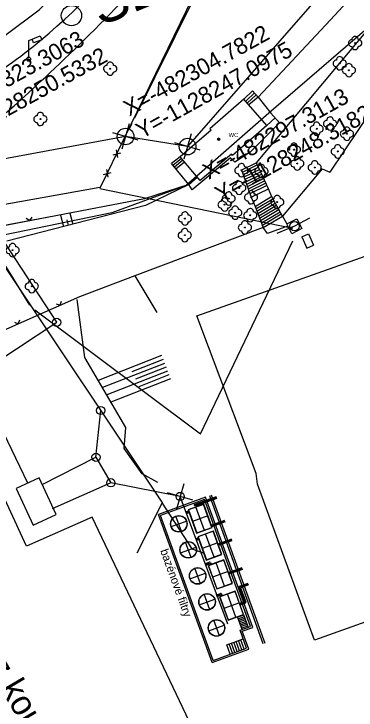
# Model space of a CAD drawing. Extents: x -483721 to -481876, y -1129170 to -1127366.
# Drawn here: x -482318.3 to -482277, y -1128316.3 to -1128232.3 of the extents above; entities that cross this region are included whole.
import ezdxf

# ---------------------------------------------------------------- set-up
doc = ezdxf.new("R2010")
doc.units = 0
for name, color, linetype in [('1 Terenni Hrany', 7, 'Continuous'), ('FILTRACE', 7, 'Continuous'), ('Hranice parcel', 7, 'Continuous'), ('kresba', 7, 'Continuous'), ('OSTATNI', 7, 'Continuous'), ('SO 01', 7, 'Continuous'), ('SO 01_zrušeno', 7, 'Continuous'), ('SO 02', 7, 'Continuous'), ('SO 02_odpad', 7, 'Continuous'), ('SO 02_plot', 7, 'Continuous'), ('SO 02_prací', 7, 'Continuous'), ('SO 02_upravená', 7, 'Continuous'), ('SO 04', 7, 'Continuous'), ('SO 07', 7, 'Continuous'), ('STROM', 7, 'Continuous'), ('U_IGP', 7, 'Continuous'), ('u_SO_POPIS_1000', 7, 'Continuous'), ('u_vytyčení', 7, 'Continuous'), ('ˇ12', 7, 'Continuous')]:
    doc.layers.add(name, color=color, linetype=linetype)

# ---------------------------------------------------------------- blocks, each defined once
blk = doc.blocks.new('STROM')
blk.add_circle((0, 0), 0.143)
for centre, start, end in [((-1.01, -0.04), 90.2896, 270.7727), ((-0.02, 1.01), 359.3339, 182.81), ((0, -0.99), 90.3571, 90.7727), ((-1.01, -0.04), 2.5539, 2.81), ((0.99, 0), 179.3339, 179.5894), ((-0.02, 1.01), 270.2896, 270.7197), ((0.99, 0), 270.3571, 90.7197), ((0, -0.99), 182.5539, 359.5894)]:
    blk.add_arc(centre, 1, start, end)
blk = doc.blocks.new('_X5')
for p, q in [((13.91, 13.06), (14.17, 13.32)), ((14.18, 12.81), (13.91, 13.07)), ((13.92, 13.02), (14.21, 13.31)), ((13.92, 13.11), (14.12, 13.31)), ((14.22, 12.81), (13.92, 13.11)), ((14.13, 12.81), (13.92, 13.03)), ((13.93, 12.98), (14.25, 13.3)), ((14.25, 12.82), (13.93, 13.15)), ((14.07, 12.83), (13.93, 12.96)), ((13.94, 12.95), (14.28, 13.29)), ((13.94, 13.18), (14.05, 13.29)), ((14.28, 12.84), (13.94, 13.18)), ((13.95, 12.92), (14.31, 13.27)), ((14.31, 12.85), (13.96, 13.21)), ((13.97, 12.9), (14.33, 13.25)), ((14.34, 12.87), (13.98, 13.23)), ((14.36, 12.9), (14, 13.25)), ((14, 12.87), (14.35, 13.23)), ((14.02, 12.85), (14.37, 13.21)), ((14.38, 12.92), (14.03, 13.27)), ((14.39, 12.95), (14.05, 13.29)), ((14.05, 12.84), (14.39, 13.18)), ((14.08, 12.82), (14.4, 13.15)), ((14.41, 12.98), (14.09, 13.3)), ((14.42, 13.02), (14.12, 13.31)), ((14.12, 12.81), (14.41, 13.11)), ((14.42, 13.06), (14.16, 13.32)), ((14.16, 12.81), (14.42, 13.07)), ((14.2, 12.81), (14.42, 13.02)), ((14.41, 13.11), (14.21, 13.31)), ((14.27, 12.83), (14.4, 12.96)), ((14.39, 13.18), (14.28, 13.29))]:
    blk.add_line(p, q)
blk = doc.blocks.new('BUDOVA')
blk.add_circle((0, -0.01), 0.253)
blk.add_blockref('_X5', (-14.17, -13.07))
blk = doc.blocks.new('LAMPA')
for p, q in [((0, 4.55), (2.79, 5.63)), ((2.79, 5.63), (3.13, 4.71)), ((0, 0.52), (0, 4.55)), ((1.17, 3.98), (0.84, 4.87)), ((3.13, 4.71), (1.17, 3.98))]:
    blk.add_line(p, q)
blk.add_circle((0, 0.02), 0.5)

msp = doc.modelspace()

# ---------------------------------------------------------------- linework, layer by layer
for p, q in [((-482307.86, -1128253.28), (-482295.68, -1128228.29)), ((-482307.9, -1128253.27), (-482358.09, -1128262.23)), ((-482307.881, -1128253.364), (-482284.63, -1128258.16)), ((-482307.87, -1128253.3), (-482307.87, -1128253.3)), ((-482303.39, -1128297.34), (-482300.38, -1128291.35))]:
    msp.add_line(p, q)
for points in [[(-482357.81, -1128262.3), (-482319.42, -1128262.72), (-482300.35, -1128291.33)], [(-482300.38, -1128291.35), (-482296.794, -1128296.846), (-482295.295, -1128297.398)]]:
    msp.add_lwpolyline(points)
at = {"layer": '1 Terenni Hrany'}
msp.add_lwpolyline([(-482352.607, -1128249.588), (-482341.55, -1128246.847), (-482332.308, -1128243.048), (-482323.52, -1128238.017), (-482315.2, -1128231.824), (-482308.051, -1128224.73), (-482304.891, -1128221.021), (-482300.175, -1128213.301)], dxfattribs=at)
at = {"layer": 'FILTRACE'}
for p, q in [((-482296.423, -1128291.481), (-482293.827, -1128290.541)), ((-482288.172, -1128308.339), (-482294.642, -1128290.464)), ((-482287.965, -1128308.264), (-482294.435, -1128290.389)), ((-482295.131, -1128290.641), (-482300.82, -1128292.7)), ((-482295.251, -1128290.897), (-482300.564, -1128292.82)), ((-482296.483, -1128291.609), (-482293.793, -1128290.635)), ((-482296.354, -1128291.669), (-482293.759, -1128290.729)), ((-482289.7, -1128306.233), (-482295.251, -1128290.897)), ((-482289.444, -1128306.353), (-482295.131, -1128290.641)), ((-482295.363, -1128291.469), (-482297.244, -1128292.15)), ((-482297.244, -1128292.15), (-482296.223, -1128294.971)), ((-482295.378, -1128291.501), (-482297.212, -1128292.165)), ((-482297.212, -1128292.165), (-482296.208, -1128294.939)), ((-482296.354, -1128291.669), (-482296.423, -1128291.481)), ((-482295.282, -1128294.631), (-482296.303, -1128291.81)), ((-482294.374, -1128294.275), (-482295.378, -1128291.501)), ((-482294.342, -1128294.29), (-482295.363, -1128291.469)), ((-482294.35, -1128310.575), (-482300.82, -1128292.7)), ((-482294.23, -1128310.319), (-482300.564, -1128292.82)), ((-482298.024, -1128294.783), (-482298.705, -1128292.902)), ((-482297.475, -1128292.393), (-482297.193, -1128292.291)), ((-482297.441, -1128292.487), (-482297.159, -1128292.385)), ((-482297.407, -1128292.581), (-482297.125, -1128292.479)), ((-482294.853, -1128292.88), (-482296.733, -1128293.56)), ((-482299.305, -1128294.183), (-482297.424, -1128293.502)), ((-482294.451, -1128293.989), (-482292.796, -1128293.39)), ((-482294.417, -1128294.083), (-482292.762, -1128293.484)), ((-482294.383, -1128294.177), (-482292.728, -1128293.578)), ((-482296.223, -1128294.971), (-482294.342, -1128294.29)), ((-482296.208, -1128294.939), (-482294.374, -1128294.275)), ((-482294.189, -1128294.713), (-482296.07, -1128295.394)), ((-482294.204, -1128294.745), (-482296.037, -1128295.409)), ((-482293.2, -1128297.519), (-482294.204, -1128294.745)), ((-482293.168, -1128297.534), (-482294.189, -1128294.713)), ((-482296.301, -1128295.637), (-482296.018, -1128295.535)), ((-482296.267, -1128295.731), (-482295.984, -1128295.629)), ((-482296.07, -1128295.394), (-482295.048, -1128298.215)), ((-482296.037, -1128295.409), (-482295.033, -1128298.183)), ((-482294.108, -1128297.875), (-482295.129, -1128295.054)), ((-482296.887, -1128297.923), (-482297.568, -1128296.043)), ((-482296.232, -1128295.825), (-482295.95, -1128295.723)), ((-482293.678, -1128296.124), (-482295.559, -1128296.804)), ((-482293.634, -1128296.246), (-482291.979, -1128295.647)), ((-482293.6, -1128296.34), (-482291.945, -1128295.741)), ((-482293.566, -1128296.434), (-482291.911, -1128295.835)), ((-482298.168, -1128297.323), (-482296.288, -1128296.643)), ((-482295.048, -1128298.215), (-482293.168, -1128297.534)), ((-482295.033, -1128298.183), (-482293.2, -1128297.519)), ((-482295.208, -1128298.656), (-482294.691, -1128298.468)), ((-482295.174, -1128298.75), (-482294.657, -1128298.562)), ((-482295.14, -1128298.844), (-482294.717, -1128298.69)), ((-482292.926, -1128298.202), (-482294.807, -1128298.883)), ((-482294.807, -1128298.883), (-482293.786, -1128301.703)), ((-482292.941, -1128298.234), (-482294.775, -1128298.898)), ((-482294.775, -1128298.898), (-482293.771, -1128301.671)), ((-482294.717, -1128298.69), (-482294.666, -1128298.831)), ((-482294.657, -1128298.562), (-482294.572, -1128298.797)), ((-482294.563, -1128298.528), (-482294.478, -1128298.763)), ((-482292.845, -1128301.363), (-482293.867, -1128298.542)), ((-482291.937, -1128301.008), (-482292.941, -1128298.234)), ((-482291.905, -1128301.023), (-482292.926, -1128298.202)), ((-482297.031, -1128300.464), (-482295.151, -1128299.783)), ((-482295.751, -1128301.064), (-482296.431, -1128299.183)), ((-482292.416, -1128299.612), (-482294.296, -1128300.293)), ((-482292.382, -1128299.706), (-482290.727, -1128299.107)), ((-482292.348, -1128299.8), (-482290.693, -1128299.201)), ((-482292.314, -1128299.894), (-482290.659, -1128299.295)), ((-482293.786, -1128301.703), (-482291.905, -1128301.023)), ((-482293.771, -1128301.671), (-482291.937, -1128301.008)), ((-482290.029, -1128301.035), (-482291.073, -1128301.413)), ((-482289.995, -1128301.129), (-482291.039, -1128301.507)), ((-482291.039, -1128301.507), (-482290.389, -1128303.303)), ((-482289.961, -1128301.223), (-482290.911, -1128301.567)), ((-482294.614, -1128304.205), (-482295.295, -1128302.324)), ((-482293.847, -1128302.417), (-482293.329, -1128302.23)), ((-482293.813, -1128302.511), (-482293.295, -1128302.324)), ((-482291.565, -1128301.963), (-482293.445, -1128302.644)), ((-482291.58, -1128301.995), (-482293.413, -1128302.659)), ((-482293.295, -1128302.324), (-482293.21, -1128302.559)), ((-482293.201, -1128302.29), (-482293.116, -1128302.525)), ((-482291.484, -1128305.124), (-482292.505, -1128302.303)), ((-482290.576, -1128304.769), (-482291.58, -1128301.995)), ((-482290.544, -1128304.784), (-482291.565, -1128301.963)), ((-482291.133, -1128301.541), (-482290.517, -1128303.243)), ((-482290.911, -1128301.567), (-482290.295, -1128303.269)), ((-482295.895, -1128303.605), (-482294.014, -1128302.924)), ((-482293.779, -1128302.605), (-482293.355, -1128302.452)), ((-482293.445, -1128302.644), (-482292.424, -1128305.465)), ((-482293.413, -1128302.659), (-482292.409, -1128305.433)), ((-482293.355, -1128302.452), (-482293.304, -1128302.593)), ((-482291.054, -1128303.374), (-482292.935, -1128304.054)), ((-482291.034, -1128303.43), (-482290.517, -1128303.243)), ((-482291, -1128303.524), (-482290.389, -1128303.303)), ((-482290.966, -1128303.618), (-482290.355, -1128303.397)), ((-482292.424, -1128305.465), (-482290.544, -1128304.784)), ((-482292.409, -1128305.433), (-482290.576, -1128304.769)), ((-482291.279, -1128305.103), (-482290.527, -1128304.831)), ((-482290.544, -1128304.784), (-482289.982, -1128306.335)), ((-482293.477, -1128307.345), (-482294.158, -1128305.465)), ((-482290.734, -1128306.608), (-482291.296, -1128305.056)), ((-482291.211, -1128305.291), (-482290.459, -1128305.019)), ((-482291.143, -1128305.479), (-482290.391, -1128305.207)), ((-482291.075, -1128305.667), (-482290.323, -1128305.395)), ((-482291.007, -1128305.855), (-482290.255, -1128305.583)), ((-482294.758, -1128306.745), (-482292.877, -1128306.065)), ((-482290.97, -1128306.693), (-482289.7, -1128306.233)), ((-482290.939, -1128306.044), (-482290.186, -1128305.771)), ((-482290.871, -1128306.232), (-482290.118, -1128305.959)), ((-482290.803, -1128306.42), (-482290.05, -1128306.147)), ((-482290.713, -1128306.813), (-482289.444, -1128306.353)), ((-482290.187, -1128308.856), (-482290.97, -1128306.693)), ((-482289.931, -1128308.975), (-482290.713, -1128306.813)), ((-482292.57, -1128308.442), (-482290.595, -1128307.727)), ((-482291.597, -1128309.366), (-482292.006, -1128308.238)), ((-482291.315, -1128309.264), (-482291.724, -1128308.136)), ((-482291.033, -1128309.162), (-482291.441, -1128308.033)), ((-482290.751, -1128309.06), (-482291.159, -1128307.931)), ((-482290.469, -1128308.958), (-482290.877, -1128307.829)), ((-482294.35, -1128310.575), (-482289.931, -1128308.975)), ((-482294.23, -1128310.319), (-482290.187, -1128308.856)), ((-482292.161, -1128309.57), (-482292.57, -1128308.442)), ((-482291.879, -1128309.468), (-482292.288, -1128308.34))]:
    msp.add_line(p, q, dxfattribs=at)
for centre, radius in [((-482296.388, -1128291.575), 0.1), ((-482298.365, -1128293.843), 1), ((-482298.365, -1128293.843), 0.975), ((-482297.228, -1128296.983), 1), ((-482297.228, -1128296.983), 0.975), ((-482296.091, -1128300.124), 1), ((-482296.091, -1128300.124), 0.975), ((-482294.954, -1128303.264), 1), ((-482294.954, -1128303.264), 0.975), ((-482293.818, -1128306.405), 1), ((-482293.818, -1128306.405), 0.975)]:
    msp.add_circle(centre, radius, dxfattribs=at)
for centre, start, end in [((-482294.657, -1128298.562), 19.89787, 109.89787), ((-482291.039, -1128301.507), 109.89787, 199.89787), ((-482293.295, -1128302.324), 19.89787, 109.89787), ((-482290.389, -1128303.303), 289.89787, 19.89787)]:
    msp.add_arc(centre, 0.1, start, end, dxfattribs=at)
at = {"layer": 'Hranice parcel'}
for points in [[(-482200.01, -1128286.72), (-482216.5, -1128237.02), (-482235.49, -1128199.44), (-482287.49, -1128244.29), (-482297.48, -1128253.01), (-482306.43, -1128256.33), (-482332.62, -1128261.72)], [(-482249.12, -1128252.06), (-482242.21, -1128270.9), (-482241.72, -1128272.17), (-482234.85, -1128291.03), (-482281.99, -1128307.88), (-482288.87, -1128289.05), (-482289.03, -1128287.78), (-482296.2, -1128268.76), (-482249.12, -1128252.06)], [(-482293.58, -1128325.11), (-482308.82, -1128293.03), (-482316.72, -1128296.54), (-482327.19, -1128273.95)]]:
    msp.add_lwpolyline(points, dxfattribs=at)
at = {"layer": 'kresba'}
for p, q in [((-482271.47, -1128223.58), (-482280.07, -1128233.03)), ((-482266.62, -1128231.16), (-482280.15, -1128251.39)), ((-482278.95, -1128238.27), (-482273.507, -1128231.722)), ((-482280.07, -1128233.03), (-482288.81, -1128242.34)), ((-482288.98, -1128250.26), (-482278.95, -1128238.27)), ((-482290.51, -1128242.59), (-482289.457, -1128241.609)), ((-482290.301, -1128242.832), (-482289.245, -1128241.848)), ((-482289.457, -1128241.609), (-482288.81, -1128242.34)), ((-482290.51, -1128242.59), (-482294.63, -1128246.18)), ((-482287.76, -1128245.79), (-482290.51, -1128242.59)), ((-482290.11, -1128243.065), (-482289.045, -1128242.074)), ((-482288.81, -1128242.34), (-482289.911, -1128243.287)), ((-482288.81, -1128242.34), (-482287.27, -1128244.28)), ((-482287.27, -1128244.28), (-482286.21, -1128245.44)), ((-482287.76, -1128245.79), (-482286.741, -1128244.859)), ((-482287.76, -1128245.79), (-482291.88, -1128249.38)), ((-482286.21, -1128245.44), (-482289.76, -1128249.01)), ((-482294.453, -1128246.351), (-482298.22, -1128249.54)), ((-482294.63, -1128246.18), (-482294.453, -1128246.351)), ((-482292.013, -1128249.231), (-482295.78, -1128252.42)), ((-482291.88, -1128249.38), (-482292.013, -1128249.231)), ((-482289.76, -1128249.01), (-482291.61, -1128250.18)), ((-482298.22, -1128249.54), (-482299.253, -1128250.368)), ((-482298.061, -1128249.742), (-482299.081, -1128250.589)), ((-482297.866, -1128249.961), (-482298.889, -1128250.81)), ((-482297.689, -1128250.186), (-482298.713, -1128251.036)), ((-482295.78, -1128252.42), (-482298.22, -1128249.54)), ((-482292.14, -1128249.66), (-482296.75, -1128253.53)), ((-482291.61, -1128250.18), (-482292.14, -1128249.66)), ((-482288.98, -1128250.26), (-482290.81, -1128251.17)), ((-482287.56, -1128253.43), (-482288.98, -1128250.26)), ((-482297.16, -1128252.89), (-482299.253, -1128250.368)), ((-482288.857, -1128250.534), (-482290.71, -1128251.455)), ((-482288.735, -1128250.808), (-482290.609, -1128251.74)), ((-482288.612, -1128251.082), (-482290.509, -1128252.025)), ((-482281.08, -1128250.99), (-482285.86, -1128256.7)), ((-482281.08, -1128250.99), (-482280.15, -1128251.39)), ((-482290.81, -1128251.17), (-482289.657, -1128254.441)), ((-482288.489, -1128251.356), (-482290.408, -1128252.31)), ((-482288.366, -1128251.63), (-482290.308, -1128252.595)), ((-482288.244, -1128251.904), (-482290.207, -1128252.88)), ((-482297.16, -1128252.89), (-482296.163, -1128251.994)), ((-482288.121, -1128252.178), (-482290.107, -1128253.165)), ((-482287.998, -1128252.452), (-482290.006, -1128253.451)), ((-482287.875, -1128252.726), (-482289.906, -1128253.736)), ((-482297.16, -1128252.89), (-482302.51, -1128254.64)), ((-482297.16, -1128252.89), (-482302.38, -1128255.43)), ((-482296.75, -1128253.53), (-482297.16, -1128252.89)), ((-482287.753, -1128253), (-482289.805, -1128254.021)), ((-482289.657, -1128254.441), (-482287.56, -1128253.43)), ((-482287.163, -1128254.369), (-482287.56, -1128253.43)), ((-482289.657, -1128254.441), (-482289.171, -1128255.545)), ((-482289.171, -1128255.545), (-482287.255, -1128254.388)), ((-482285.86, -1128256.7), (-482287.163, -1128254.369)), ((-482302.51, -1128254.64), (-482319.95, -1128257.97)), ((-482289.061, -1128255.828), (-482287.032, -1128254.604)), ((-482288.951, -1128256.112), (-482286.885, -1128254.866)), ((-482288.841, -1128256.396), (-482286.739, -1128255.128)), ((-482302.38, -1128255.43), (-482319.12, -1128259.74)), ((-482289.171, -1128255.545), (-482288.18, -1128258.1)), ((-482288.731, -1128256.68), (-482286.592, -1128255.39)), ((-482288.62, -1128256.964), (-482286.446, -1128255.652)), ((-482288.51, -1128257.248), (-482286.299, -1128255.914)), ((-482312.641, -1128256.574), (-482312.28, -1128257.979)), ((-482311.495, -1128256.356), (-482311.152, -1128257.689)), ((-482288.4, -1128257.532), (-482286.153, -1128256.176)), ((-482288.335, -1128257.843), (-482286.015, -1128256.443)), ((-482288.18, -1128258.1), (-482285.86, -1128256.7)), ((-482285.86, -1128256.7), (-482285.325, -1128257.635)), ((-482282.597, -1128256.963), (-482284.41, -1128257.93)), ((-482311.88, -1128257.169), (-482311.709, -1128257.832)), ((-482288.18, -1128258.1), (-482303.69, -1128263.91)), ((-482287.68, -1128258.79), (-482288.18, -1128258.1)), ((-482285.57, -1128258.04), (-482287.68, -1128258.79)), ((-482284.41, -1128257.93), (-482286.527, -1128258.811)), ((-482285.202, -1128257.926), (-482285.57, -1128258.04)), ((-482283.54, -1128259.2), (-482282.72, -1128258.83)), ((-482283.54, -1128259.2), (-482282.923, -1128260.567)), ((-482282.72, -1128258.83), (-482282.103, -1128260.197)), ((-482295.733, -1128282.999), (-482284.607, -1128259.692)), ((-482282.923, -1128260.567), (-482282.103, -1128260.197)), ((-482316.349, -1128267.44), (-482319.24, -1128262.733)), ((-482303.69, -1128263.91), (-482310.35, -1128266.46)), ((-482303.69, -1128263.91), (-482301, -1128268.345)), ((-482310.35, -1128266.46), (-482326.91, -1128273.79)), ((-482315.735, -1128268.033), (-482295.733, -1128282.999))]:
    msp.add_line(p, q, dxfattribs=at)
msp.add_lwpolyline([(-482285.344, -1128257.644), (-482284.128, -1128257.028), (-482283.524, -1128258.22), (-482284.741, -1128258.836)], close=True, dxfattribs=at)
msp.add_circle((-482284.41, -1128257.93), 0.574, dxfattribs=at)
for points in [[(-482386.87, -1128244.71), (-482337.34, -1128245.3), (-482304.59, -1128221.02), (-482292.62, -1128190.48), (-482292.122, -1128185.833), (-482386.87, -1128244.71), (-482292.122, -1128185.833)], [(-482371.94, -1128252.14), (-482352.872, -1128253.171), (-482333.7, -1128247.75), (-482316.47, -1128237.78), (-482302, -1128223.19), (-482292.54, -1128205.83), (-482288.95, -1128186.24), (-482371.94, -1128252.14), (-482288.95, -1128186.24)], [(-482371.94, -1128252.14), (-482347.59, -1128254.37), (-482324.64, -1128248.35), (-482320.83, -1128246.15), (-482296.38, -1128222.8), (-482288.05, -1128206.72), (-482284.38, -1128189.12), (-482371.94, -1128252.14), (-482284.38, -1128189.12)], [(-482384.18, -1128239.51), (-482331.25, -1128235.13), (-482309.86, -1128216.34), (-482300, -1128190.05), (-482384.18, -1128239.51), (-482300, -1128190.05)]]:
    msp.add_open_spline(points, degree=3, dxfattribs=at)
at = {"layer": 'SO 01'}
msp.add_lwpolyline([(-482202.984, -1128231.154), (-482212.198, -1128214.378), (-482227.058, -1128219.745), (-482256.094, -1128201.089), (-482297.311, -1128248.318), (-482304.782, -1128247.098), (-482364.54, -1128258.181), (-482368.011, -1128257.278)], dxfattribs=at)
for centre in [(-482304.782, -1128247.098), (-482297.311, -1128248.318)]:
    msp.add_circle(centre, 1, dxfattribs=at)
at = {"layer": 'SO 01_zrušeno'}
for p, q in [((-482306.293, -1128249.296), (-482305.354, -1128249.06)), ((-482305.915, -1128248.707), (-482305.77, -1128249.645)), ((-482307.07, -1128251.081), (-482306.926, -1128252.019)), ((-482307.449, -1128251.67), (-482306.51, -1128251.433))]:
    msp.add_line(p, q, dxfattribs=at)
at = {"layer": 'SO 02'}
msp.add_line((-482308.358, -1128285.81), (-482306.567, -1128288.89), dxfattribs=at)
for centre in [(-482313.093, -1128269.525), (-482307.791, -1128280.167), (-482308.358, -1128285.81), (-482306.567, -1128288.89), (-482298.201, -1128290.541)]:
    msp.add_circle(centre, 0.5, dxfattribs=at)
at = {"layer": 'SO 02_odpad'}
msp.add_lwpolyline([(-482314.848, -1128289.086), (-482308.358, -1128285.81), (-482307.791, -1128280.167)], dxfattribs=at)
at = {"layer": 'SO 02_plot'}
for p, q in [((-482313.846, -1128256.8), (-482325.458, -1128259.012)), ((-482316.764, -1128256.965), (-482316.342, -1128257.237)), ((-482316.342, -1128257.237), (-482316.074, -1128256.824)), ((-482310.35, -1128266.46), (-482321.159, -1128271.244)), ((-482312.682, -1128267.451), (-482312.514, -1128266.987)), ((-482313.155, -1128267.281), (-482312.682, -1128267.451)), ((-482318.205, -1128269.501), (-482317.747, -1128269.688)), ((-482317.747, -1128269.688), (-482317.56, -1128269.229))]:
    msp.add_line(p, q, dxfattribs=at)
at = {"layer": 'SO 02_prací'}
msp.add_lwpolyline([(-482292.45, -1128305.957), (-482298.201, -1128290.541), (-482306.567, -1128288.89), (-482313.636, -1128292.02)], dxfattribs=at)
at = {"layer": 'SO 02_upravená'}
for points in [[(-482313.093, -1128269.525), (-482321.654, -1128256.489), (-482322.763, -1128252.491)], [(-482316.585, -1128288.949), (-482322.857, -1128275.937), (-482313.093, -1128269.525)]]:
    msp.add_lwpolyline(points, dxfattribs=at)
at = {"layer": 'SO 04'}
for points in [[(-482296.386, -1128230.092), (-482303.694, -1128244.895)], [(-482304.036, -1128245.588), (-482304.339, -1128246.201)]]:
    msp.add_lwpolyline(points, dxfattribs=at)
at = {"layer": 'SO 07'}
msp.add_lwpolyline([(-482315.197, -1128288.305), (-482317.973, -1128289.592), (-482315.929, -1128294.001), (-482313.153, -1128292.715)], close=True, dxfattribs=at)
at = {"layer": 'U_IGP'}
msp.add_circle((-482311.318, -1128232.513), 1.223, dxfattribs=at)
at = {"layer": 'u_vytyčení'}
for p, q in [((-482304.342, -1128245.569), (-482305.222, -1128248.627)), ((-482303.253, -1128247.537), (-482306.311, -1128246.658)), ((-482296.872, -1128246.789), (-482297.751, -1128249.847)), ((-482295.782, -1128248.758), (-482298.84, -1128247.878)), ((-482297.761, -1128289.012), (-482298.641, -1128292.07)), ((-482296.672, -1128290.981), (-482299.73, -1128290.101))]:
    msp.add_line(p, q, dxfattribs=at)
at = {"layer": 'ˇ12'}
for p, q in [((-482309.71, -1128273.76), (-482310.63, -1128266.76)), ((-482304.74, -1128282.23), (-482309.71, -1128273.76)), ((-482300.46, -1128273.54), (-482308.09, -1128276.53)), ((-482300.09, -1128274.48), (-482307.57, -1128277.4)), ((-482300.27, -1128274.01), (-482304.05, -1128275.49)), ((-482299.73, -1128275.41), (-482307.06, -1128278.28)), ((-482299.91, -1128274.94), (-482303.61, -1128276.39)), ((-482299.55, -1128275.87), (-482303.18, -1128277.29)), ((-482299.36, -1128276.34), (-482306.55, -1128279.15)), ((-482304.94, -1128284.74), (-482304.74, -1128282.23)), ((-482302.78, -1128287.82), (-482304.94, -1128284.74)), ((-482300.89, -1128288.85), (-482302.78, -1128287.82))]:
    msp.add_line(p, q, dxfattribs=at)

# ---------------------------------------------------------------- block references
at = {"layer": 'OSTATNI', "xscale": 0.5, "yscale": 0.5}
msp.add_blockref('LAMPA', (-482316.47, -1128237.78), dxfattribs=at)
at = {"layer": 'STROM'}
for name, p, xscale, yscale in [('STROM', (-482277.09, -1128235.82), 0.40000000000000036, 0.40000000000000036), ('STROM', (-482278.95, -1128238.27), 0.40000000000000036, 0.40000000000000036), ('STROM', (-482306.64, -1128238.92), 0.4000000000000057, 0.4000000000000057), ('STROM', (-482277.84, -1128239.11), 0.40000000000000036, 0.40000000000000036), ('STROM', (-482315.06, -1128244.99), 0.4000000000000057, 0.4000000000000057), ('STROM', (-482280.11, -1128245.54), 0.40000000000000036, 0.40000000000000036), ('STROM', (-482281.73, -1128246.17), 0.40000000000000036, 0.40000000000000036), ('STROM', (-482278.09, -1128246.77), 0.40000000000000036, 0.40000000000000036), ('BUDOVA', (-482293.561, -1128247.419), 0.5, 0.5), ('STROM', (-482284.47, -1128248.69), 0.3999999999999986, 0.3999999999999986), ('STROM', (-482279.19, -1128248.9), 0.40000000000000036, 0.40000000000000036), ('STROM', (-482284.07, -1128250.36), 0.3999999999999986, 0.3999999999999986), ('STROM', (-482281.97, -1128250.84), 0.40000000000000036, 0.40000000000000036), ('STROM', (-482290.81, -1128251.17), 0.3999999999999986, 0.3999999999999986), ('STROM', (-482288.39, -1128251.27), 0.3999999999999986, 0.3999999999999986), ('STROM', (-482291.08, -1128253.31), 0.3999999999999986, 0.3999999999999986), ('STROM', (-482289.657, -1128254.441), 0.3999999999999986, 0.3999999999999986), ('STROM', (-482292.35, -1128254.59), 0.3999999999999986, 0.3999999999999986), ('STROM', (-482286.49, -1128255.01), 0.3999999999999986, 0.3999999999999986), ('STROM', (-482292.84, -1128255.32), 0.3999999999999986, 0.3999999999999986), ('STROM', (-482291.56, -1128256.3), 0.3999999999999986, 0.3999999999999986), ('STROM', (-482289.75, -1128256.6), 0.3999999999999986, 0.3999999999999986), ('STROM', (-482297.62, -1128257), 0.3999999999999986, 0.3999999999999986), ('STROM', (-482290.39, -1128258.08), 0.3999999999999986, 0.3999999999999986), ('STROM', (-482297.64, -1128259.01), 0.3999999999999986, 0.3999999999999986), ('STROM', (-482318.41, -1128260.82), 0.3999999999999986, 0.3999999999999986), ('STROM', (-482316.095, -1128265.165), 0.3999999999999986, 0.3999999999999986)]:
    msp.add_blockref(name, p, dxfattribs=dict(at, xscale=xscale, yscale=yscale))

# ---------------------------------------------------------------- texts
at = {"layer": 'FILTRACE'}
msp.add_text('bazénové filtry', height=1, rotation=289.87908, dxfattribs=at).set_placement((-482300.623, -1128297.078))
at = {"layer": 'kresba'}
msp.add_text('WC', height=0.5, dxfattribs=at).set_placement((-482292.347, -1128247.172))
at = {"layer": 'U_IGP'}
msp.add_text('S2', height=5, rotation=22.52893, dxfattribs=at).set_placement((-482307.862, -1128233.843))
at = {"layer": 'u_SO_POPIS_1000'}
for s, p in [('SO 02 - Prací vody z koupaliště', (-482339.308, -1128280.807)), ('SO 07 - Provozní objekt technologie', (-482343.777, -1128283.382)), ('PS 01 - Technologie čištění pracích vod', (-482349.342, -1128286.541)), ('PS 02 - Elektroinstalace technologie čištění', (-482354.451, -1128289.475))]:
    msp.add_text(s, height=3, rotation=300.48063, dxfattribs=at).set_placement(p)
at = {"layer": 'u_vytyčení'}
for s, p in [('X=-482304.7822', (-482304.34, -1128244.71)), ('X=-482323.3063', (-482326.673, -1128245.417)), ('Y=-1128247.0975', (-482302.842, -1128247.417)), ('Y=-1128250.5332', (-482325.175, -1128248.124)), ('X=-482297.3113', (-482294.787, -1128252.345)), ('Y=-1128248.3182', (-482293.289, -1128255.052))]:
    msp.add_text(s, height=1.96875, rotation=28.95592, dxfattribs=at).set_placement(p)

doc.saveas('drawing.dxf')
